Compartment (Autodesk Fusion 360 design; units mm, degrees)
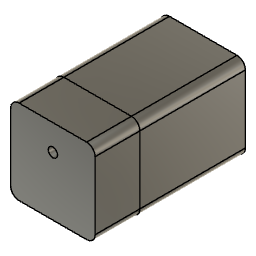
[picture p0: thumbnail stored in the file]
sketch "Sketch1" plane through (0, 0, 0) normal (0, 1, 0) x axis (1, 0, 0)
  line L1 (-5, -5) -> (5, -5)
  line L2 (-5, 5) -> (-5, -5)
  line L3 (5, 5) -> (-5, 5)
  line L4 (5, -5) -> (5, 5)
  line L5 (0, 5) -> (0, -5)
  circle C1 centre (0, -1.95) radius 0.55
  circle C2 centre (0, 0) radius 2.5
  circle C3 centre (0, 0) radius 4.25
  circle C4 centre (0, 0) radius 3.25
  circle C5 centre (0, 0) radius 4.1
  circle C6 centre (0, 0) radius 3.4
  point P8 (0, -5)
  point P9 (0, 5)
  point P10 (0, 0)
  point P1 (0, 0)
  point P3 (0, 0)
  point P2 (0, -1.95)
  point P11 (0, -2.5)
  point P12 (0, 0)
  point P16 (0, -3.4)
  point P17 (0, -4.1)
  point P18 (0, -3.25)
  point P19 (0, -4.25)
  point P6 (-5, 5)
  point P7 (5, 5)
  horizontal L1
  vertical L2
  horizontal L3
  vertical L4
  midpoint L1 P8
  midpoint L3 P9
  equal L1 L4
  midpoint L5 P10
  coincident P1 P10
  coincident P3 P10
  coincident P2 L5
  coincident L5 P11
  coincident C2 P11
  coincident C1 P11
  coincident P10 P12
  concentric C3 C4
  concentric C2 C5
  concentric C3 C6
  coincident C6 P16
  coincident L5 P16
  coincident C5 P17
  coincident L5 P17
  coincident C4 P18
  coincident L5 P18
  coincident C3 P19
  coincident L5 P19
  dimension "d2" diameter C2 = 5
  dimension "d3" diameter C1 = 1.1
  dimension "d17" distance P6 P7 = 10
  dimension "d18" diameter C4 = 6.5
  dimension "d19" diameter C3 = 8.5
  dimension "d20" distance P16 P18 = 0.15
  dimension "d21" distance P17 P19 = 0.15
  dimension "d30" distance P2 P8 = 3.05
extrude "Extrude1" new body sketch "Sketch1" profile of C2 L1 L2 L3 L4 C3 C4 C5 C6 along normal blind 5 bodies "Body (1cm,1.1mm)"
extrude "Extrude2" new body sketch "Sketch1" profile of C1 C2 L1 L2 L3 L4 C3 C4 C5 C6 against normal blind 3.9 bodies "Lid (1cm,1.1mm, top)"
mirror "Mirror2" mirrorStitchTolerance 0.1
combine "Combine2"
extrude "Extrude4" cut sketch "Sketch1" profile of C3 C4 along normal blind 5
extrude "Extrude5" add sketch "Sketch1" profile of C5 C6 along normal blind 4.8
extrude "Extrude7" add sketch "Sketch1" profile of C2 C4 C6 along normal blind 1.4
combine "Combine4"
fillet "Fillet1" radius 1
named bodies: "Body (1cm,1.1mm)", "Lid (1cm,1.1mm, top)"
